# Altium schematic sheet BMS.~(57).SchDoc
size A3; SheetNumber: 8; SheetTotal: 15
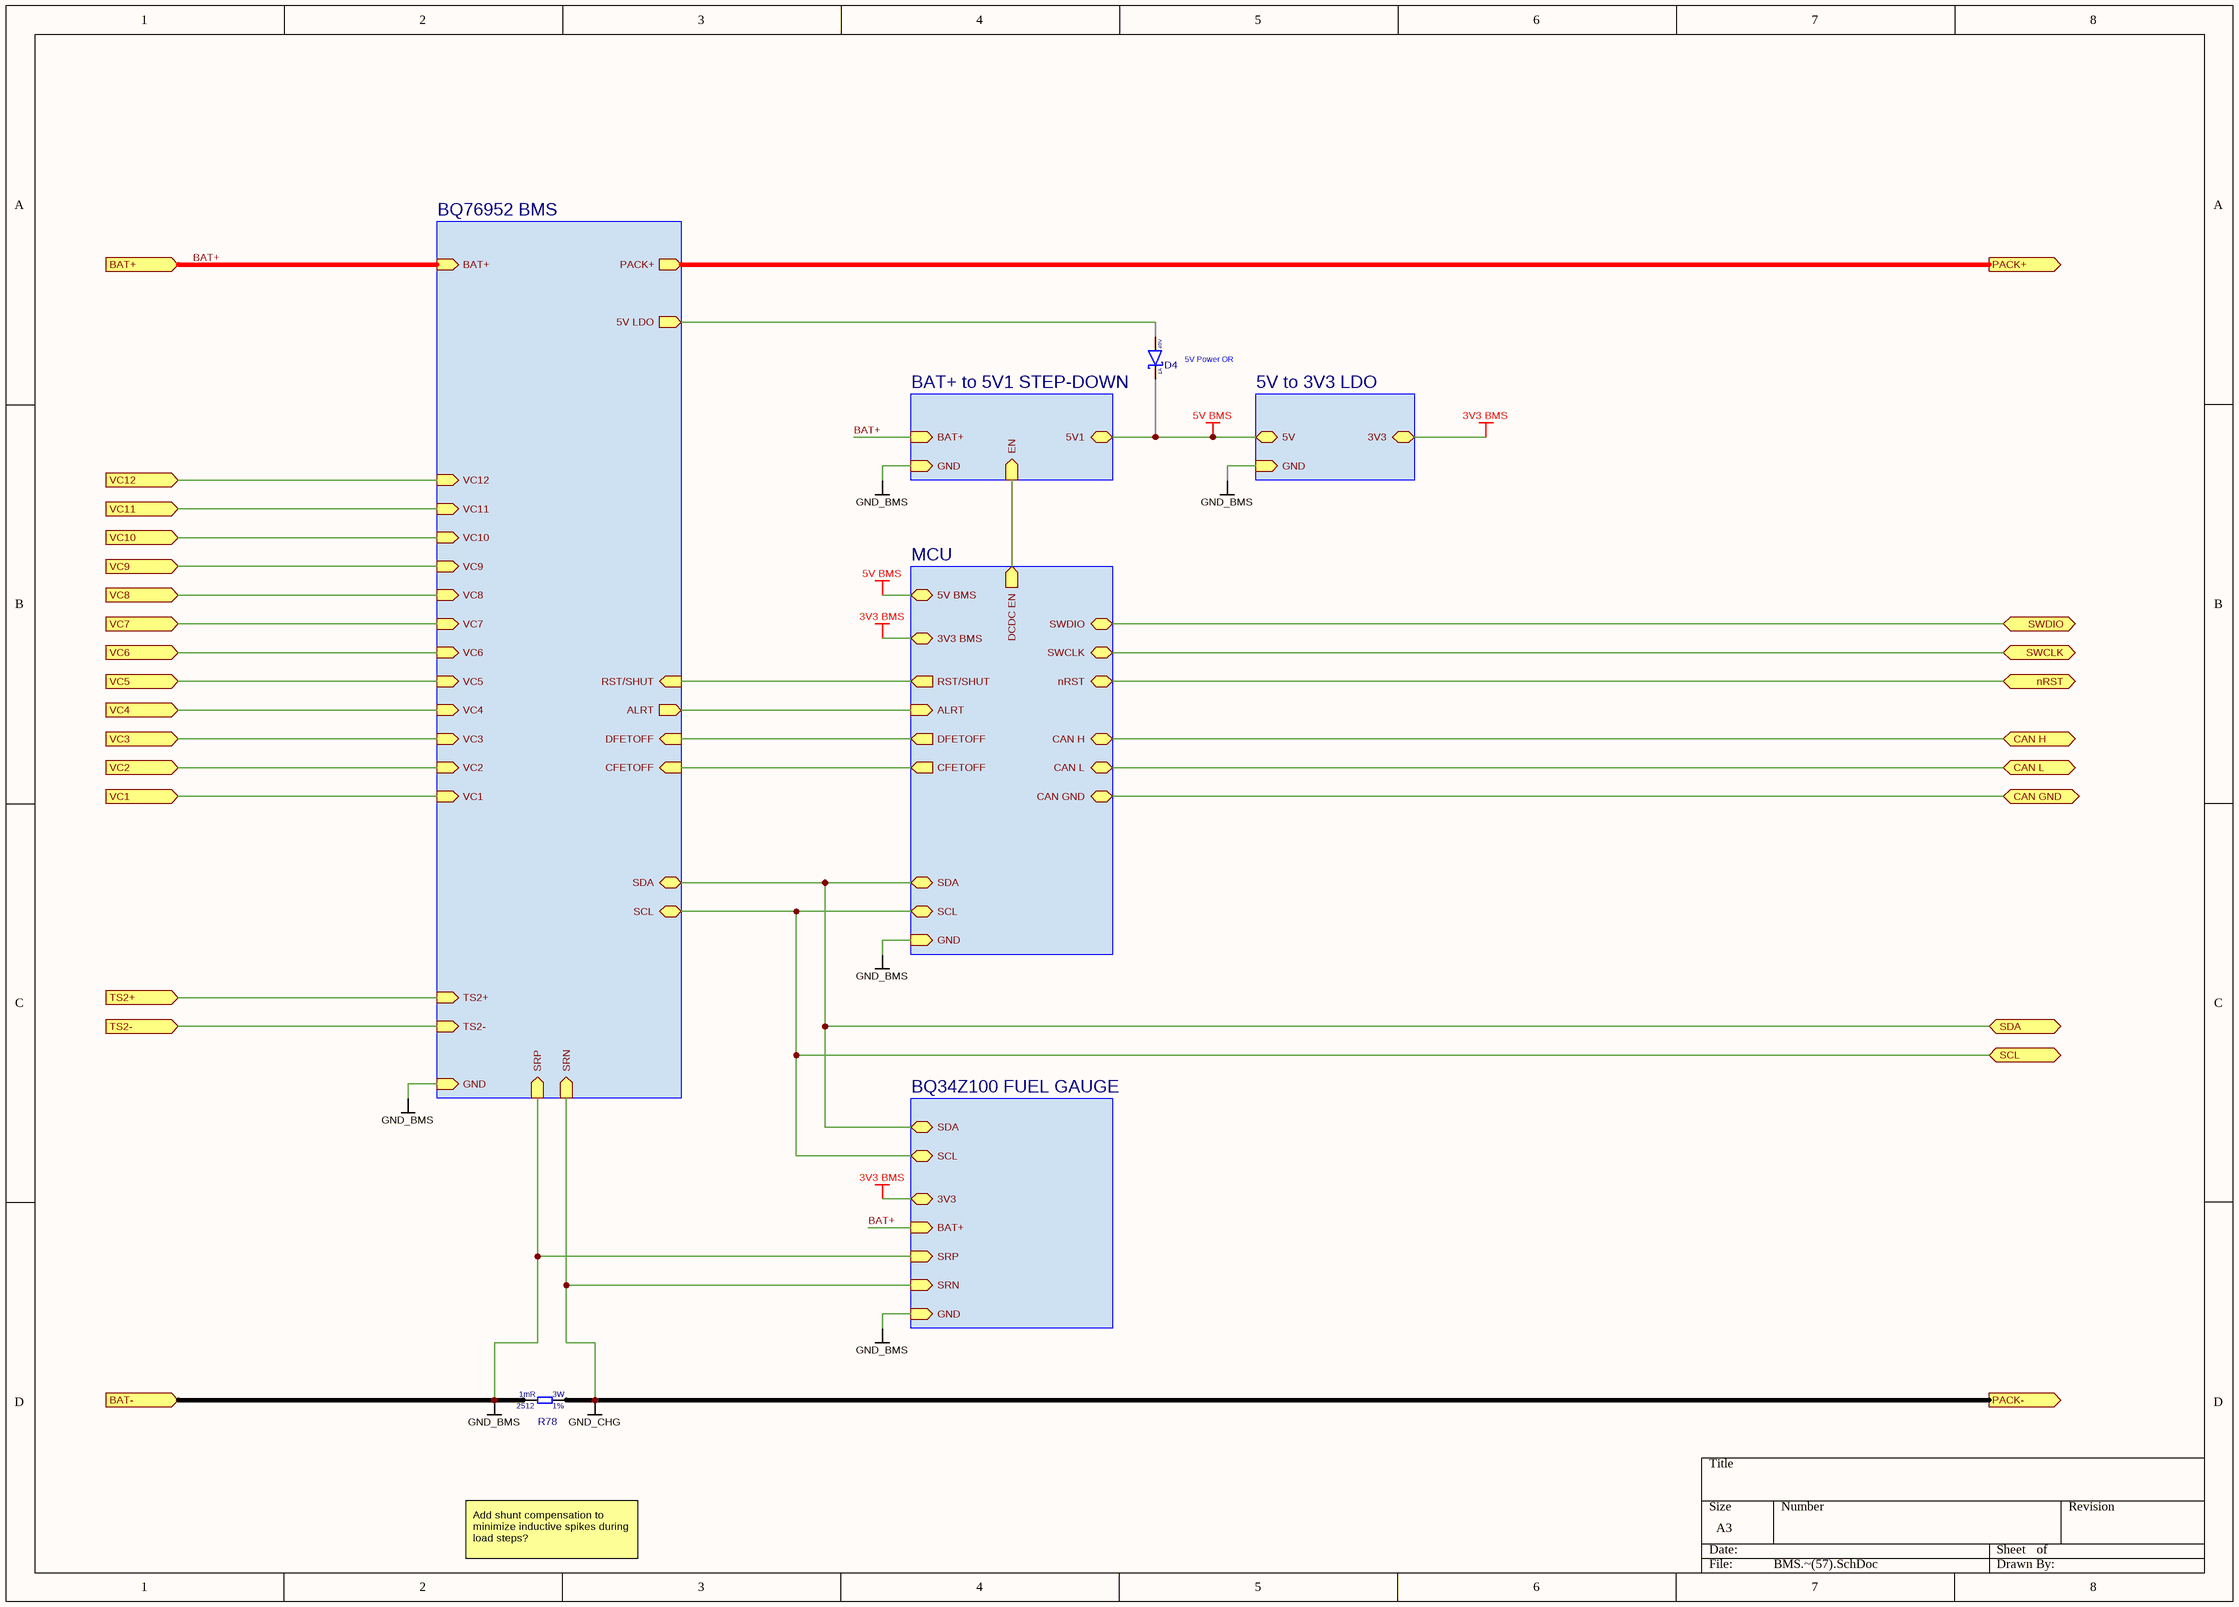
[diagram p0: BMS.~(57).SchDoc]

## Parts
D4  Forward Current: 1A  Reverse Voltage: 40V  [SOD-323]  (hidden comment: 1N5819WS)
R78  Resistance Tolerance: 1%  Resistance: 1mR  Power Rating: 3W  Case Code (Imperial): 2512  [2512 Shunt]  (hidden comment: HoYLR2512E-3W-1mR-1%)

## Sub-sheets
5V to 3V3 LDO = 5V to 3V3 LDO.SchDoc: 5V (bidir), 3V3 (bidir), GND (in)
BAT+ to 5V1 STEP-DOWN = BAT+ to 5V1 STEP-DOWN.SchDoc: 5V1 (bidir), BAT+ (in), EN (in), GND (in)
BQ34Z100 FUEL GAUGE = BQ34Z100 FUEL GAUGE.SchDoc: SRP (in), SRN (in), SDA (bidir), SCL (bidir), BAT+ (in), GND (in), 3V3 (bidir)
BQ76952 BMS = BQ76952 BMS.SchDoc: VC12 (in), VC11 (in), VC10 (in), VC9 (in), VC8 (in), VC7 (in), VC6 (in), VC5 (in), VC4 (in), VC3 (in), VC2 (in), VC1 (in), TS2+ (in), TS2- (in), BAT+ (in), PACK+ (out), 5V LDO (out), SRP (in), SRN (in), SDA (bidir), SCL (bidir), ALRT (out), DFETOFF (in), CFETOFF (in), RST/SHUT (in), GND (in)
MCU = MCU.SchDoc: DCDC EN (out), 5V BMS (bidir), 3V3 BMS (bidir), SDA (bidir), SCL (bidir), ALRT (in), DFETOFF (out), CFETOFF (out), RST/SHUT (out), CAN H (bidir), CAN L (bidir), GND (in), nRST (bidir), SWCLK (bidir), SWDIO (bidir), CAN GND (bidir)

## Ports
BAT+ (in, see Arhitecture[3B], BAT+ to 5V1 STEP-DOWN[3B], BQ34Z100 FUEL GAUGE[3A], BQ76952 BMS[1A], ESD battery side[5A], ESD system side[3A]), BAT- (in, see Arhitecture[3C], ESD battery side[5C]), CAN GND (bidir, see Arhitecture[4B], ESD system side[3B], MCU[8B]), CAN H (bidir, see Arhitecture[4B], ESD system side[3B], MCU[8A]), CAN L (bidir, see Arhitecture[4B], ESD system side[3B], MCU[8B]), nRST (bidir, see Arhitecture[3C], MCU[8C]), PACK+ (out, see Arhitecture[4B], BQ76952 BMS[8A], Charger BQ25756[1A], CHARGER[1B], Power distribution[3A]), PACK- (out, see Arhitecture[4C], CHARGER[1C], ESD system side[3C]), SCL (bidir, see Arhitecture[4C], BQ34Z100 FUEL GAUGE[5B], BQ76952 BMS[7C], MCU[1B]), SDA (bidir, see Arhitecture[4C], BQ34Z100 FUEL GAUGE[5B], BQ76952 BMS[7C], MCU[1B]), SWCLK (bidir, see Arhitecture[3C], MCU[8C]), SWDIO (bidir, see Arhitecture[3C], MCU[8C]), TS2+ (in, see Arhitecture[3C], BQ76952 BMS[3C], ESD battery side[5C]), TS2- (in, see Arhitecture[3C], BQ76952 BMS[3C], ESD battery side[5C]), VC1 (in, see Arhitecture[3B], BQ76952 BMS[1C], ESD battery side[5B]), VC2 (in, see Arhitecture[3B], BQ76952 BMS[1C], ESD battery side[5B]), VC3 (in, see Arhitecture[3B], BQ76952 BMS[1C], ESD battery side[5B]), VC4 (in, see Arhitecture[3B], BQ76952 BMS[1C], ESD battery side[5B]), VC5 (in, see Arhitecture[3B], BQ76952 BMS[1C], ESD battery side[5B]), VC6 (in, see Arhitecture[3B], BQ76952 BMS[1C], ESD battery side[5B]), VC7 (in, see Arhitecture[3B], BQ76952 BMS[1C], ESD battery side[5B]), VC8 (in, see Arhitecture[3B], BQ76952 BMS[1B], ESD battery side[5B]), VC9 (in, see Arhitecture[3B], BQ76952 BMS[1B], ESD battery side[5B]), VC10 (in, see Arhitecture[3B], BQ76952 BMS[1B], ESD battery side[5B]), VC11 (in, see Arhitecture[3B], BQ76952 BMS[1B], ESD battery side[5B]), VC12 (in, see Arhitecture[3B], BQ76952 BMS[1B], ESD battery side[5B])

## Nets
3V3 BMS: sheet BQ34Z100 FUEL GAUGE/3V3, sheet MCU/3V3 BMS, sheet 5V to 3V3 LDO/3V3
5V BMS: D4.K ; sheet MCU/5V BMS, sheet BAT+ to 5V1 STEP-DOWN/5V1, sheet 5V to 3V3 LDO/5V
GND_BMS: R78.1 ; port BAT-, sheet BQ76952 BMS/SRP, sheet BQ76952 BMS/GND, sheet BQ34Z100 FUEL GAUGE/SRP, sheet BQ34Z100 FUEL GAUGE/GND, sheet MCU/GND, sheet BAT+ to 5V1 STEP-DOWN/GND, sheet 5V to 3V3 LDO/GND
GND_CHG: R78.2 ; port PACK-, sheet BQ76952 BMS/SRN, sheet BQ34Z100 FUEL GAUGE/SRN
BAT+: port BAT+, sheet BQ76952 BMS/BAT+, sheet BQ34Z100 FUEL GAUGE/BAT+, sheet BAT+ to 5V1 STEP-DOWN/BAT+
CAN GND: port CAN GND, sheet MCU/CAN GND
CAN H: port CAN H, sheet MCU/CAN H
CAN L: port CAN L, sheet MCU/CAN L
nRST: port nRST, sheet MCU/nRST
PACK+: port PACK+, sheet BQ76952 BMS/PACK+
SCL: port SCL, sheet BQ76952 BMS/SCL, sheet BQ34Z100 FUEL GAUGE/SCL, sheet MCU/SCL
SDA: port SDA, sheet BQ76952 BMS/SDA, sheet BQ34Z100 FUEL GAUGE/SDA, sheet MCU/SDA
SWCLK: port SWCLK, sheet MCU/SWCLK
SWDIO: port SWDIO, sheet MCU/SWDIO
TS2+: port TS2+, sheet BQ76952 BMS/TS2+
TS2-: port TS2-, sheet BQ76952 BMS/TS2-
VC1: port VC1, sheet BQ76952 BMS/VC1
VC2: port VC2, sheet BQ76952 BMS/VC2
VC3: port VC3, sheet BQ76952 BMS/VC3
VC4: port VC4, sheet BQ76952 BMS/VC4
VC5: port VC5, sheet BQ76952 BMS/VC5
VC6: port VC6, sheet BQ76952 BMS/VC6
VC7: port VC7, sheet BQ76952 BMS/VC7
VC8: port VC8, sheet BQ76952 BMS/VC8
VC9: port VC9, sheet BQ76952 BMS/VC9
VC10: port VC10, sheet BQ76952 BMS/VC10
VC11: port VC11, sheet BQ76952 BMS/VC11
VC12: port VC12, sheet BQ76952 BMS/VC12
NetD4_A: D4.A ; sheet BQ76952 BMS/5V LDO
(unnamed): sheet BQ76952 BMS/ALRT, sheet MCU/ALRT
(unnamed): sheet BQ76952 BMS/DFETOFF, sheet MCU/DFETOFF  [a separate net that carries the same name]
(unnamed): sheet BQ76952 BMS/CFETOFF, sheet MCU/CFETOFF  [a separate net that carries the same name]
(unnamed): sheet BQ76952 BMS/RST/SHUT, sheet MCU/RST/SHUT  [a separate net that carries the same name]
(unnamed): sheet MCU/DCDC EN, sheet BAT+ to 5V1 STEP-DOWN/EN  [a separate net that carries the same name]

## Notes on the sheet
- (near D4) 5V Power OR
- Add shunt compensation to minimize inductive spikes during load steps?

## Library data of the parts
D4 = 1N5819WS: Schottky 40V 1A 600mVf SOD-323; Manufacturer: Guangdong Hottech
R78 = HoYLR2512E-3W-1mR-1%: RES 1mR 2512 3W 1%; Manufacturer: Miliohm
